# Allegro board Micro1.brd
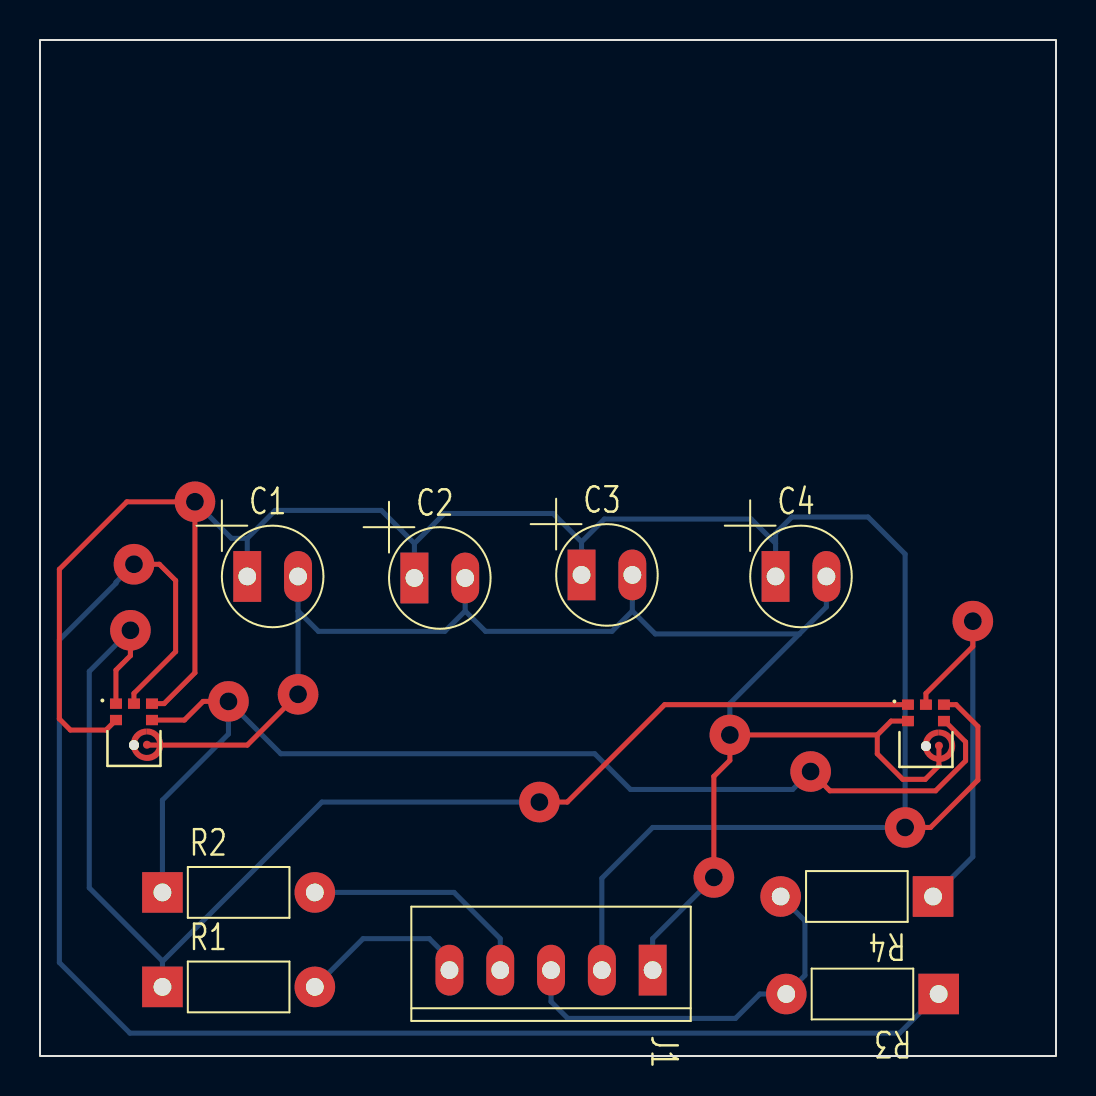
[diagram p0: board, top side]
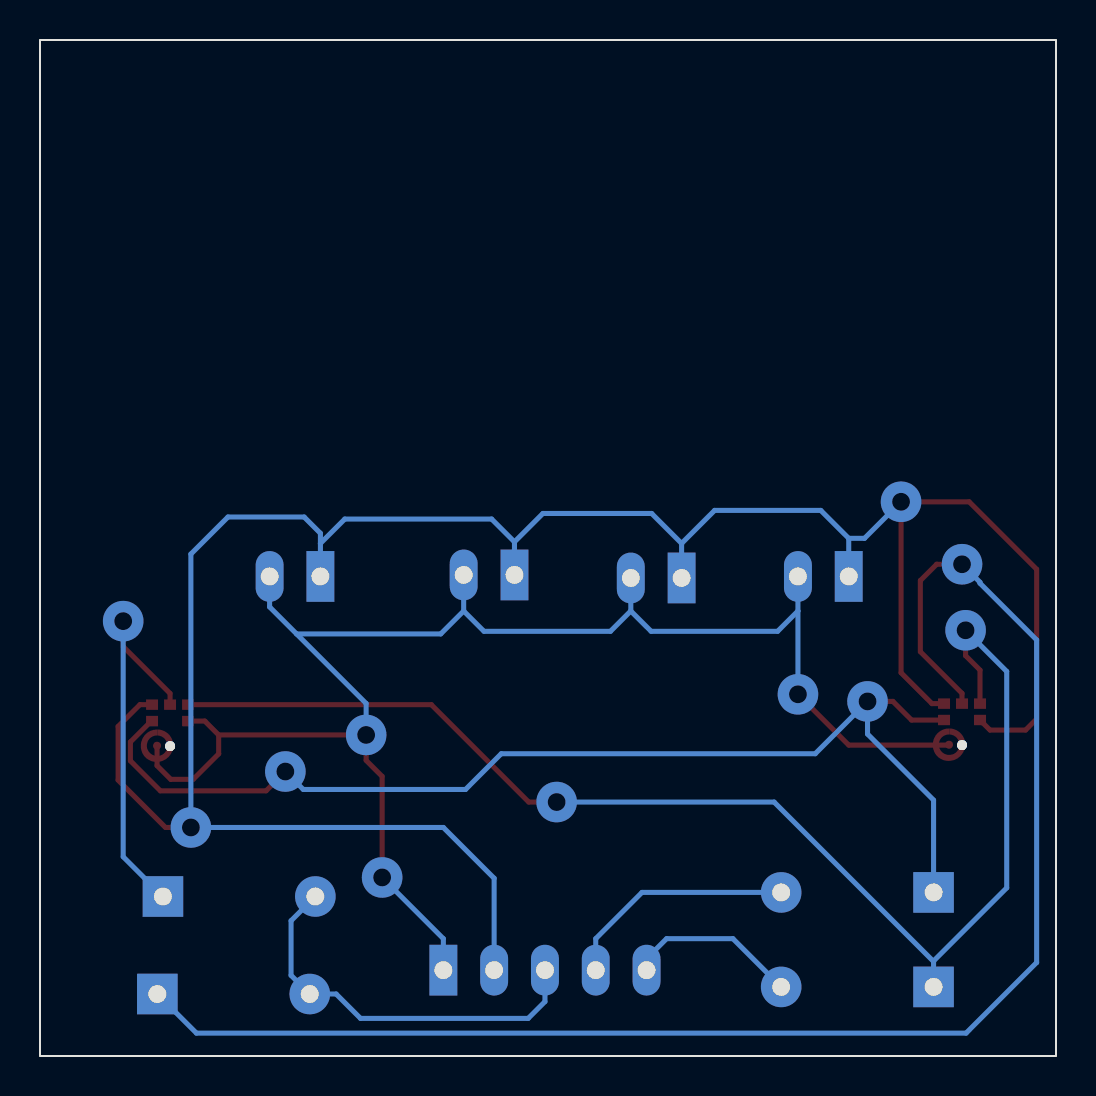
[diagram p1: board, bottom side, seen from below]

Outline 50.8 x 50.8 mm; copper layers: TOP, BOTTOM. Coordinates in mm from the lower left corner of the outline.
Outline path: rectangle 0,0 50.8,50.8

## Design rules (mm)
constraint set DEFAULT: min track width 0.254

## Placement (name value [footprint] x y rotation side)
C1  1uf  [GU-CAPCYL100]  10.36 23.98 0 top
C2  220pf  [GU-CAPCYL100]  18.72 23.9 0 top
C3  1uf  [GU-CAPCYL100]  27.08 24.05 0 top
C4  220pf  [GU-CAPCYL100]  36.78 23.98 0 top
J1  HEADER 5  [GU-MOLEX5]  30.63 4.29 270 top
R1  47  [GU-RC300]  6.12 3.45 0 top
R2  47  [GU-RC300]  6.12 8.18 0 top
R3  47  [GU-RC300]  44.93 3.1 180 top
R4  47  [GU-RC300]  44.65 7.98 180 top
U1  SPH0645LM4H-B  [MIC_SPH0645LM4H-B]  4.7 15.54 0 top
U2  SPH0645LM4H-B  [MIC_SPH0645LM4H-B]  44.3 15.49 0 top

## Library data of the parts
C1-C4 = CAPACITOR
J1 = HEADER 5
R1-R4 = RESISTOR
U1 U2 = SPH0645LM4H-B

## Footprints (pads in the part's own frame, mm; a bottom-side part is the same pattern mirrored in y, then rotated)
GU-CAPCYL100
  rect 1.397x2.54 hole 0.889: 1(0,0)
  oval 1.397x2.54 hole 0.889: 2(2.54,0)
GU-MOLEX5
  rect 2.54x1.397 hole 0.889: 1(0,0)
  oval 2.54x1.397 hole 0.889: 2(0,-2.54) 3(0,-5.08) 4(0,-7.62) 5(0,-10.16)
GU-RC300
  rect 2.032x2.032 hole 0.889: 1(0,0)
  round 2.032 hole 0.889: 2(7.62,0)
MIC_SPH0645LM4H-B
  round 0.5 hole 0.5 unplated: (0,0)
  rect 0.6x0.522 smd: 1(-0.9,2.074) 2(-0.9,1.252) 4(0.9,1.252) 5(0.9,2.074) 6(0,2.074)
  custom 0.405x0.405 smd: 3(0.65,0.02)

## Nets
GND_POWER: C1.2 C2.2 C3.2 C4.2 J1.1 U1.3 U2.2 U2.3
VDD: C1.1 C2.1 C3.1 C4.1 J1.2 U1.2 U1.5 U2.5
BLCK: J1.4 R2.2
DATA: J1.3 R3.2 R4.2
WC: J1.5 R1.2
N01929: R3.1 U1.6
N01947: R4.1 U2.6
N02065: R1.1 U1.1(WS) U2.1(WS)
N02132: R2.1 U1.4 U2.4

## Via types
v1: diameter 2.032, hole 0.889, TOP to BOTTOM, 11 vias

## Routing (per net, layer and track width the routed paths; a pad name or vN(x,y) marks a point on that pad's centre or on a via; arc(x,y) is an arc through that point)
GND_POWER: length 83.5
  TOP w0.254: 44.93,15.49 U2.3 44.95,14.52 44.26,13.83 43.14,13.83 41.86,15.11 41.86,16.05 ; 41.86,16.05 42.56,16.75 U2.2 ; 41.86,16.05 v1(34.49,16.05) 34.49,14.78 33.69,13.98 v1(33.69,8.93) ; U1.3 5.37,15.54 10.36,15.54 v1(12.9,18.08)
  BOTTOM w0.254: 29.62,22.25 30.76,21.1 37.97,21.1 ; 29.62,22.25 28.6,21.23 22.28,21.23 21.26,22.25 ; 29.62,22.25 C3.2 ; 37.97,21.1 39.32,22.45 C4.2 ; 37.97,21.1 34.49,17.63 v1(34.49,16.05) ; 21.26,22.25 20.24,21.23 13.92,21.23 12.9,22.25 ; 21.26,22.25 C2.2 ; J1.1 30.63,5.87 v1(33.69,8.93) ; v1(12.9,18.08) 12.9,22.25 ; 12.9,22.25 C1.2
VDD: length 122.5
  TOP w0.254: U2.5 45.8,17.57 46.89,16.48 46.89,13.8 44.53,11.43 v1(43.26,11.43) ; U1.2 3.3,16.3 1.52,16.3 0.97,16.85 0.97,24.34 4.34,27.71 v1(7.75,27.71) 7.75,19.16 6.2,17.62 U1.5
  BOTTOM w0.254: 27.08,25.7 C3.1 ; 27.08,25.7 28.22,26.85 35.56,26.85 36.78,25.63 ; 27.08,25.7 25.65,27.13 20.22,27.13 18.72,25.63 ; 18.72,25.63 C2.1 ; 18.72,25.63 17.07,27.28 11.76,27.28 10.36,25.88 ; 10.36,25.88 C1.1 ; 10.36,25.88 9.58,25.88 v1(7.75,27.71) ; 36.78,25.63 36.78,26.14 37.59,26.95 41.4,26.95 43.26,25.1 v1(43.26,11.43) 30.63,11.43 28.09,8.89 J1.2 ; 36.78,25.63 C4.1
BLCK: length 11.8
  BOTTOM w0.254: J1.4 23.01,5.87 20.7,8.18 R2.2
DATA: length 20
  BOTTOM w0.254: R4.2 38.25,6.76 38.25,4.03 R3.2 35.99,3.1 34.77,1.88 26.39,1.88 25.55,2.72 J1.3
WC: length 8.7
  BOTTOM w0.254: R1.2 16.15,5.87 19.47,5.87 20.47,4.86 J1.5
N01929: length 77.1
  TOP w0.254: U1.6 4.7,18.13 6.78,20.22 6.78,23.77 5.97,24.59 v1(4.7,24.59)
  BOTTOM w0.254: v1(4.7,24.59) 3.8,23.69 3.8,23.64 0.97,20.81 0.97,4.67 4.5,1.14 42.98,1.14 R3.1
N01947: length 19.7
  TOP w0.254: U2.6 44.3,18.13 46.64,20.47 v1(46.64,21.74)
  BOTTOM w0.254: v1(46.64,21.74) 46.64,9.96 R4.1
N02065: length 66.8
  TOP w0.254: U1.1 3.8,19.29 4.52,20.02 v1(4.52,21.29) ; v1(24.97,12.7) 26.36,12.7 31.23,17.57 U2.1
  BOTTOM w0.254: v1(24.97,12.7) 14.09,12.7 6.12,4.72 ; 6.12,4.72 R1.1 ; 6.12,4.72 6.12,4.75 2.46,8.41 2.46,19.23 v1(4.52,21.29)
N02132: length 57.7
  TOP w0.254: U1.4 7.22,16.8 8.15,17.73 v1(9.42,17.73) ; v1(38.53,14.22) 39.5,13.26 44.78,13.26 46.28,14.76 46.28,15.7 45.24,16.75 U2.4
  BOTTOM w0.254: R2.1 6.12,12.8 9.42,16.1 v1(9.42,17.73) 12.04,15.11 27.74,15.11 29.52,13.33 37.63,13.33 v1(38.53,14.22)
